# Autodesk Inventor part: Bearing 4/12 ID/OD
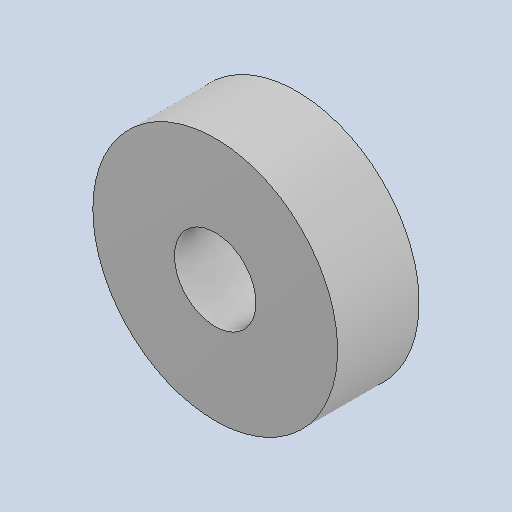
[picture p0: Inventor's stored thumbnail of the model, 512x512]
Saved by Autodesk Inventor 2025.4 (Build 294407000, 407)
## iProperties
Created: 2026-09
Part Number: Bearing 4/12 ID/OD
Material: Generic
Document SubType Name: Modeling
Designer: AdminForWorker
Density: 1 g/cm^3
Appearance: Default
Title: Bearing 4/12 ID/OD v1
Author: AdminForWorker
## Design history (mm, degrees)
feature "Body1"
body "Solid1"
